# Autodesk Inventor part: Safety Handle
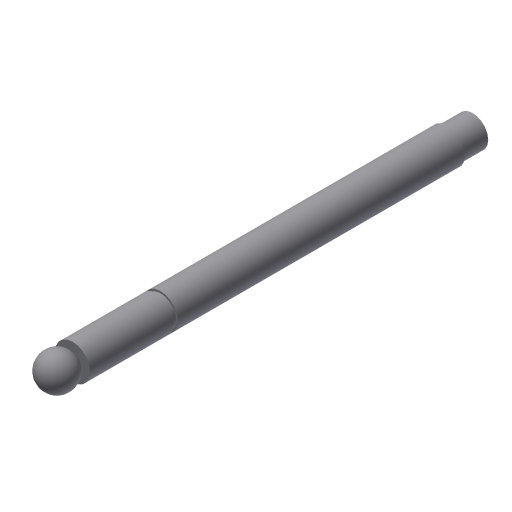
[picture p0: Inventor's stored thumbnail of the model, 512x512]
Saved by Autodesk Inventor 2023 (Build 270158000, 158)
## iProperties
Shininess: 77.0
Length Units: 11269
Angle Units: 11279
Time Units: 11290
Mass Units: 11283
Length Display Precision: 3
Angle Display Precision: 2
Created: 2002-02
Part Number: Safety Handle
Document SubType Name: Modeling
Designer: ***
Density: 1 g/cm^3
Material: Generic
Appearance: Default
Density: 0.0
Volumn: 0.0
Area: 0.0
PropertySet Name: Model Information
Control State: 0
Master: False
Checked Out: False
Author: ***
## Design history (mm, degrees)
sketch "Sketch1"
  geometry: L1 (0, 205)-(8, 205); L2 (8, 205)-(8, 192); L3 (8, 192)-(9, 192); L4 (9, 192)-(9, 45); L5 (9, 45)-(8, 45); L6 (8, 45)-(8, 43); L7 (8, 43)-(9, 43); L8 (9, 43)-(9, 0); L9 (9, 0)-(0, 0); L10 (0, 0)-(0, 205)
  constraints: 20 end point, 7 parallel, 1 collinear, 1 horizontal, 1 perpendicular
  dimensions: "d0" = 13 distance of L1.end L2.end; "d1" = 2 distance of L4.end L7.end; "d2" = 43 distance of L7.end L8.end; "d3" = 205 distance of L9.end L1.start; "d4" = 16 diameter of L2 L10; "d5" = 18 diameter of L4 L10; "d6" = 16 diameter of L6.end L10
revolve "Revolution1" sketch "Sketch1" stored, may be unused: angle "d7" = 90 deg
sketch "Sketch2"
  geometry: L1 (0, 1)-(0, -17); L2 (-9, 0)-(9, 0) reference; A1 r 9 centre (0, -8) between (0, -17) and (0, 1)
  constraints: 2 end point, 2 point on circle, 1 centre point, 1 midpoint, 1 vertical
  dimensions: "d8" = 9 radius of A1; "d9" = 1 distance from line of L2 L1.start
revolve "Revolution2" sketch "Sketch2" stored, may be unused: angle "d10" = 90 deg
body "Solid1"
